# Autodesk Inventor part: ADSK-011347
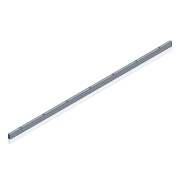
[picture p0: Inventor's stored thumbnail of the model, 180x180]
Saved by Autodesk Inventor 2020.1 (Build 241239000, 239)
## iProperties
Created: 1999-11
Part Number: ADSK-011347
Material: Pearson Aluminium
Description: Thomson shaft spacer,aluminum
Document SubType Name: Modeling
Designer: glanglot
Density: 2.71 g/cm^3
Appearance: Pearson-Aluminum
Mass: 847.425 g
Surface Area: 843.926 cm^2
Volume: 312.703 cm^3
Company: Pearson Packaging Systems
Control State: 0
Master: False
Checked Out: False
Shininess: 35.0
Length Units: 11269
Angle Units: 11279
Time Units: 11290
Mass Units: 11283
Length Display Precision: 3
Angle Display Precision: 2
Compacted: True
Cutlength: 42
Material Desc: FLAT,ALUM,0.500X01.000
Material_Number: A084013
Dimensions: 12,5x25x1067 mm
Mass: 0,847 kg
Density: 2.71
Volumn: 321.83873360747833
Area: 859.535971277
PropertySet Name: Model Information
Author: glanglot
Revision Number: -
Title: Thomson shaft spacer,aluminum
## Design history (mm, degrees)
node "Rectangular Pattern1" dims "d24" = 70 (= QH), "d26" = 152.4 (= SH)
node "Solide1"
  node "Extrusion1" dims "d4" = 1067, "d5" = 0
  node "Hole2" dims "d18" = 6.6, "d19" = 9.525, "d20" = 6.35, "d21" = 60 deg, "d22" = 19.05, "d23" = 118 deg, "d27" = 6
sketch "Sketch1"
  geometry: L1 (0, 0)-(12.5, 0); L2 (12.5, 0)-(12.5, -25); L3 (0, -25)-(0, 0); L4 (0, -25)-(6.25, -22.725); L5 (12.5, -25)-(6.25, -22.725); 1 further point
  constraints: 10 end point, 2 equal length, 1 coincident, 1 horizontal, 1 parallel, 1 perpendicular
  dimensions: "d0" = 12.5 distance of L1.start L1.end; "d1" = 25 distance of L3.start L1.start; "d2" = 70 deg angle of L4 L3
sketch "Sketch3"
  geometry: L1 (0, -1067)-(12.5, -1067) reference; L2 (12.5, 0)-(0, 0) reference; L3 (6.25, 0)-(6.25, -1067); 1 further point
  constraints: 2 end point, 2 midpoint, 1 point on line
  dimensions: "d17" = 76 distance from line of point (6.25, -76) L2
node "Corps solides"
node "Corps surfaciques"
other parameters: "SH" = 152.4 [user parameter; used in 1 equation term]
